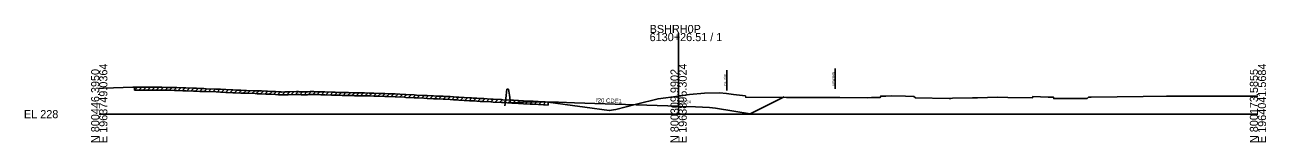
# Model space of a CAD drawing. Extents: x -26 to 1986619, y -10 to 827846.
# Drawn here: x -25.7 to 402.8, y 10490.3 to 10530.9 of the extents above; entities that cross this region are included whole.
import ezdxf

# ---------------------------------------------------------------- set-up
doc = ezdxf.new("R2010")
doc.units = 0
for name, color, linetype in [('Default', 7, 'Continuous'), ('RD_EX_Road', 7, 'Continuous'), ('RD_PD_ALT2_TrvlWay', 7, 'Continuous'), ('RD_PD_ALT5_LnLine', 7, 'Continuous'), ('RD_PD_ALT5_TrvlWay', 7, 'Continuous'), ('RD_PD_PaveDit', 7, 'Continuous'), ('RD_Sketch2', 7, 'Continuous'), ('RD_XS_ExRW', 7, 'Continuous'), ('RD_XS_NewRW', 7, 'Continuous')]:
    doc.layers.add(name, color=color, linetype=linetype)

msp = doc.modelspace()

# ---------------------------------------------------------------- linework, layer by layer
at = {"layer": 'RD_EX_Road'}
for p, q in [((200, 10500), (200, 10528.02)), ((0, 10500), (200, 10500)), ((200, 10500), (400, 10500))]:
    msp.add_line(p, q, dxfattribs=at)
at = {"layer": 'RD_PD_ALT5_LnLine'}
msp.add_lwpolyline([(0, 10508.87), (1.52, 10508.93), (4.94, 10509.05), (11.58, 10509.3), (12.32, 10509.3), (12.8, 10509.29), (13.3, 10509.34), (14.23, 10509.34), (15.37, 10509.34), (16.45, 10509.34), (17.13, 10509.34), (17.88, 10509.33), (18.87, 10509.31), (19.86, 10509.3), (21.57, 10509.28), (23.13, 10509.26), (24.28, 10509.25), (26, 10509.21), (26.8, 10509.18), (28.88, 10509.11), (29.87, 10509.08), (32.52, 10508.96), (33.06, 10508.94), (33.56, 10508.92), (34.75, 10508.86), (36.16, 10508.81), (36.93, 10508.78), (40.34, 10508.65), (41.83, 10508.59), (43.75, 10508.51), (46.1, 10508.39), (47.2, 10508.34), (48.91, 10508.28), (50.87, 10508.21), (53.82, 10508.1), (54.51, 10508.07), (56.05, 10508), (57.45, 10507.94), (58.07, 10507.92), (59.47, 10507.87), (60.85, 10507.79), (61.91, 10507.72), (62.16, 10507.68), (62.66, 10507.65), (63.08, 10507.63), (64.01, 10507.67), (65.2, 10507.68), (68.05, 10507.84), (68.68, 10507.79), (68.96, 10507.73), (69.66, 10507.72), (70.11, 10507.72), (70.8, 10507.71), (71.77, 10507.69), (72.07, 10507.76), (72.76, 10507.77), (74.13, 10507.77), (74.95, 10507.75), (76.52, 10507.7), (77.93, 10507.66), (80.17, 10507.59), (81.42, 10507.56), (82.55, 10507.52), (83.82, 10507.49), (84.92, 10507.46), (86.05, 10507.43), (87.52, 10507.4), (87.87, 10507.39), (88.22, 10507.38), (89.63, 10507.36), (91.54, 10507.31), (93.18, 10507.27), (94.82, 10507.23), (96.76, 10507.18), (98.64, 10507.11), (99.89, 10507.05), (102.2, 10506.96), (105.35, 10506.81), (105.85, 10506.79), (108.68, 10506.64), (109.51, 10506.59), (112.03, 10506.48), (113.17, 10506.43), (115.38, 10506.33), (116.81, 10506.26), (118.73, 10506.16), (119.56, 10506.12), (121.09, 10506.04), (122.33, 10505.96), (123.26, 10505.91), (124.13, 10505.86), (125.92, 10505.76), (127.84, 10505.64), (128.5, 10505.6), (129.13, 10505.56), (130.35, 10505.48), (131.51, 10505.41), (132.78, 10505.35), (135.16, 10505.21), (136, 10505.17), (138.81, 10505.02), (139.36, 10504.99), (142.48, 10504.81), (142.97, 10504.79), (146.42, 10504.6), (148.73, 10504.49), (149.8, 10504.43), (153.31, 10504.27), (153.99, 10504.26), (154.95, 10504.11), (163.34, 10503.02), (167.58, 10502.43), (176.05, 10501.21), (178.36, 10501.66), (185.49, 10503.49), (192.93, 10505.29), (200, 10506.24), (203.8, 10506.75), (208.97, 10507.29), (214.17, 10507.31), (216.56, 10507.17), (218.99, 10506.84), (223.09, 10506.27), (223.19, 10505.82), (237.25, 10505.78), (240.1, 10505.77), (247.06, 10505.8), (255.61, 10505.75), (265.3, 10505.66), (266.64, 10505.71), (268.44, 10505.75), (269.61, 10505.78), (269.77, 10506.23), (271.54, 10506.25), (273.49, 10506.27), (278.37, 10506.22), (281.21, 10506.13), (281.77, 10505.67), (293.38, 10505.45), (294.03, 10505.46), (294.58, 10505.48), (301.46, 10505.58), (302.65, 10505.61), (303.19, 10505.63), (310.11, 10505.81), (313.63, 10505.8), (322.19, 10505.69), (322.3, 10506.14), (327.53, 10505.87), (327.95, 10505.87), (328.29, 10505.86), (329.43, 10505.82), (329.53, 10505.38), (341, 10505.39), (341.5, 10505.84), (342.48, 10505.85), (360.36, 10506.11), (368.41, 10506.24), (393.13, 10506.23), (400, 10506.23)], dxfattribs=at)
at = {"layer": 'RD_PD_PaveDit'}
for p, q in [((12.2, 10508.3), (13.24, 10509.33)), ((12.2, 10508.3), (12.2, 10509.3)), ((12.2, 10508.3), (12.32, 10508.3)), ((12.32, 10508.3), (12.8, 10508.29)), ((12.8, 10508.29), (13.3, 10508.34)), ((13.3, 10508.34), (14.23, 10508.34)), ((13.7, 10508.34), (14.7, 10509.34)), ((14.23, 10508.34), (15.37, 10508.34)), ((15.2, 10508.34), (16.2, 10509.34)), ((15.37, 10508.34), (16.45, 10508.34)), ((16.45, 10508.34), (17.13, 10508.34)), ((16.7, 10508.34), (17.69, 10509.33)), ((17.13, 10508.34), (17.88, 10508.33)), ((17.88, 10508.33), (18.87, 10508.31)), ((18.2, 10508.32), (19.19, 10509.31)), ((18.87, 10508.31), (19.86, 10508.3)), ((19.7, 10508.3), (20.69, 10509.29)), ((19.86, 10508.3), (21.57, 10508.28)), ((21.2, 10508.28), (22.19, 10509.27)), ((21.57, 10508.28), (23.13, 10508.26)), ((22.7, 10508.26), (23.69, 10509.25)), ((23.13, 10508.26), (24.28, 10508.25)), ((24.2, 10508.25), (25.18, 10509.23)), ((24.28, 10508.25), (26, 10508.21)), ((25.7, 10508.21), (26.67, 10509.19)), ((26, 10508.21), (26.8, 10508.18)), ((26.8, 10508.18), (28.88, 10508.11)), ((27.2, 10508.17), (28.17, 10509.14)), ((28.7, 10508.12), (29.66, 10509.08)), ((28.88, 10508.11), (29.87, 10508.08)), ((29.87, 10508.08), (32.52, 10507.96)), ((30.2, 10508.06), (31.16, 10509.02)), ((31.7, 10508), (32.66, 10508.95)), ((32.52, 10507.96), (33.06, 10507.94)), ((33.06, 10507.94), (33.56, 10507.92)), ((33.2, 10507.93), (34.16, 10508.89)), ((33.56, 10507.92), (34.75, 10507.86)), ((34.7, 10507.87), (35.66, 10508.83)), ((34.75, 10507.86), (36.16, 10507.81)), ((36.16, 10507.81), (36.93, 10507.78)), ((36.2, 10507.81), (37.16, 10508.77)), ((36.93, 10507.78), (40.34, 10507.65)), ((37.7, 10507.75), (38.66, 10508.71)), ((39.2, 10507.69), (40.16, 10508.66)), ((40.34, 10507.65), (41.83, 10507.59)), ((40.7, 10507.64), (41.66, 10508.6)), ((42.2, 10507.58), (43.16, 10508.53)), ((43.7, 10507.51), (44.65, 10508.46)), ((45.2, 10507.44), (46.15, 10508.39)), ((46.7, 10507.36), (47.66, 10508.33)), ((48.2, 10507.31), (49.17, 10508.27)), ((49.7, 10507.26), (50.67, 10508.22)), ((51.2, 10507.2), (52.16, 10508.16)), ((52.7, 10507.14), (53.66, 10508.1)), ((54.2, 10507.08), (55.16, 10508.04)), ((55.7, 10507.02), (56.66, 10507.98)), ((57.2, 10506.95), (58.16, 10507.92)), ((58.7, 10506.9), (59.66, 10507.86)), ((60.2, 10506.83), (61.14, 10507.77)), ((61.7, 10506.73), (62.62, 10507.66)), ((63.2, 10506.64), (64.23, 10507.67)), ((64.7, 10506.67), (65.74, 10507.71)), ((66.2, 10506.73), (67.26, 10507.8)), ((67.7, 10506.82), (68.67, 10507.79)), ((69.2, 10506.72), (70.19, 10507.71)), ((70.7, 10506.71), (71.68, 10507.69)), ((72.2, 10506.76), (73.21, 10507.77)), ((73.7, 10506.77), (74.68, 10507.76)), ((75.2, 10506.74), (76.17, 10507.71)), ((76.7, 10506.69), (77.67, 10507.66)), ((78.2, 10506.65), (79.17, 10507.62)), ((41.83, 10507.59), (43.75, 10507.51)), ((43.75, 10507.51), (46.1, 10507.39)), ((46.1, 10507.39), (47.2, 10507.34)), ((47.2, 10507.34), (48.91, 10507.28)), ((48.91, 10507.28), (50.87, 10507.21)), ((50.87, 10507.21), (53.82, 10507.1)), ((53.82, 10507.1), (54.51, 10507.07)), ((54.51, 10507.07), (56.05, 10507)), ((56.05, 10507), (57.45, 10506.94)), ((57.45, 10506.94), (58.07, 10506.92)), ((58.07, 10506.92), (59.47, 10506.87)), ((59.47, 10506.87), (60.85, 10506.79)), ((60.85, 10506.79), (61.91, 10506.72)), ((61.91, 10506.72), (62.16, 10506.68)), ((62.16, 10506.68), (62.66, 10506.65)), ((62.66, 10506.65), (63.08, 10506.63)), ((63.08, 10506.63), (64.01, 10506.67)), ((64.01, 10506.67), (65.2, 10506.68)), ((65.2, 10506.68), (68.05, 10506.84)), ((68.05, 10506.84), (68.68, 10506.79)), ((68.68, 10506.79), (68.96, 10506.73)), ((68.96, 10506.73), (69.66, 10506.72)), ((69.66, 10506.72), (70.11, 10506.72)), ((70.11, 10506.72), (70.8, 10506.71)), ((70.8, 10506.71), (71.77, 10506.69)), ((71.77, 10506.69), (72.07, 10506.76)), ((72.07, 10506.76), (72.76, 10506.77)), ((72.76, 10506.77), (74.13, 10506.77)), ((74.13, 10506.77), (74.95, 10506.75)), ((74.95, 10506.75), (76.52, 10506.7)), ((76.52, 10506.7), (77.93, 10506.66)), ((77.93, 10506.66), (80.17, 10506.59)), ((79.7, 10506.61), (80.67, 10507.58)), ((80.17, 10506.59), (81.42, 10506.56)), ((81.2, 10506.56), (82.17, 10507.53)), ((81.42, 10506.56), (82.55, 10506.52)), ((82.55, 10506.52), (83.82, 10506.49)), ((82.7, 10506.52), (83.67, 10507.49)), ((83.82, 10506.49), (84.92, 10506.46)), ((84.2, 10506.48), (85.17, 10507.45)), ((84.92, 10506.46), (86.05, 10506.43)), ((85.7, 10506.43), (86.68, 10507.41)), ((86.05, 10506.43), (87.52, 10506.4)), ((87.2, 10506.4), (88.18, 10507.38)), ((87.52, 10506.4), (87.87, 10506.39)), ((87.87, 10506.39), (88.22, 10506.38)), ((88.22, 10506.38), (89.63, 10506.36)), ((88.7, 10506.37), (89.68, 10507.36)), ((89.63, 10506.36), (91.54, 10506.31)), ((90.2, 10506.34), (91.18, 10507.32)), ((91.54, 10506.31), (93.18, 10506.27)), ((91.7, 10506.31), (92.68, 10507.29)), ((93.18, 10506.27), (94.82, 10506.23)), ((93.2, 10506.27), (94.18, 10507.25)), ((94.7, 10506.24), (95.67, 10507.21)), ((94.82, 10506.23), (96.76, 10506.18)), ((96.2, 10506.2), (97.17, 10507.16)), ((96.76, 10506.18), (98.64, 10506.11)), ((97.7, 10506.14), (98.66, 10507.1)), ((98.64, 10506.11), (99.89, 10506.05)), ((99.2, 10506.08), (100.16, 10507.04)), ((99.89, 10506.05), (102.2, 10505.96)), ((100.7, 10506.02), (101.66, 10506.98)), ((102.2, 10505.96), (103.16, 10506.91)), ((102.2, 10505.96), (105.35, 10505.81)), ((103.7, 10505.89), (104.66, 10506.84)), ((105.2, 10505.82), (106.15, 10506.77)), ((105.35, 10505.81), (105.85, 10505.79)), ((105.85, 10505.79), (108.68, 10505.64)), ((106.7, 10505.74), (107.65, 10506.69)), ((108.2, 10505.66), (109.15, 10506.61)), ((108.68, 10505.64), (109.51, 10505.59)), ((109.51, 10505.59), (112.03, 10505.48)), ((109.7, 10505.59), (110.66, 10506.54)), ((111.2, 10505.52), (112.16, 10506.47)), ((112.03, 10505.48), (113.17, 10505.43)), ((112.7, 10505.45), (113.66, 10506.41)), ((113.17, 10505.43), (115.38, 10505.33)), ((114.2, 10505.38), (115.16, 10506.34)), ((115.38, 10505.33), (116.81, 10505.26)), ((115.7, 10505.31), (116.65, 10506.26)), ((116.81, 10505.26), (118.73, 10505.16)), ((117.2, 10505.24), (118.15, 10506.19)), ((118.7, 10505.16), (119.65, 10506.12)), ((118.73, 10505.16), (119.56, 10505.12)), ((119.56, 10505.12), (121.09, 10505.04)), ((120.2, 10505.09), (121.15, 10506.03)), ((121.09, 10505.04), (122.33, 10504.96)), ((121.7, 10505), (122.64, 10505.95)), ((122.33, 10504.96), (123.26, 10504.91)), ((123.2, 10504.91), (124.15, 10505.86)), ((123.26, 10504.91), (124.13, 10504.86)), ((124.13, 10504.86), (125.92, 10504.76)), ((124.7, 10504.83), (125.65, 10505.77)), ((125.92, 10504.76), (127.84, 10504.64)), ((126.2, 10504.74), (127.14, 10505.68)), ((127.7, 10504.65), (128.64, 10505.59)), ((127.84, 10504.64), (128.5, 10504.6)), ((128.5, 10504.6), (129.13, 10504.56)), ((129.13, 10504.56), (130.35, 10504.48)), ((129.2, 10504.55), (130.14, 10505.49)), ((130.35, 10504.48), (131.51, 10504.41)), ((130.7, 10504.46), (131.65, 10505.41)), ((131.51, 10504.41), (132.78, 10504.35)), ((132.2, 10504.38), (133.15, 10505.33)), ((132.78, 10504.35), (135.16, 10504.21)), ((133.7, 10504.3), (134.65, 10505.24)), ((135.16, 10504.21), (136, 10504.17)), ((135.2, 10504.21), (136.15, 10505.16)), ((136, 10504.17), (138.81, 10504.02)), ((136.7, 10504.13), (137.65, 10505.08)), ((138.2, 10504.05), (139.15, 10505)), ((138.81, 10504.02), (139.36, 10503.99)), ((139.36, 10503.99), (142.48, 10503.81)), ((139.7, 10503.97), (140.65, 10504.92)), ((141.2, 10503.89), (142.15, 10504.83)), ((142.48, 10503.81), (142.97, 10503.79)), ((142.7, 10503.8), (143.65, 10504.75)), ((142.97, 10503.79), (146.42, 10503.6)), ((144.2, 10503.72), (145.15, 10504.67)), ((145.7, 10503.64), (146.65, 10504.59)), ((146.42, 10503.6), (148.73, 10503.49)), ((147.2, 10503.56), (148.15, 10504.52)), ((148.7, 10503.49), (149.65, 10504.44)), ((148.73, 10503.49), (149.8, 10503.43)), ((149.8, 10503.43), (153.31, 10503.27)), ((150.2, 10503.41), (151.15, 10504.37)), ((151.7, 10503.34), (152.65, 10504.3)), ((153.2, 10503.27), (154.16, 10504.23)), ((154.95, 10504.11), (154.95, 10503.11)), ((153.31, 10503.27), (153.99, 10503.26)), ((153.99, 10503.26), (154.95, 10503.11))]:
    msp.add_line(p, q, dxfattribs=at)
at = {"layer": 'RD_Sketch2'}
msp.add_lwpolyline([(140, 10502.91), (140.33, 10505.42), (140.75, 10508.58), (141.25, 10508.58), (141.58, 10506.51), (142, 10503.91), (146.5, 10504.08), (152.02, 10504.3), (158.49, 10504.09), (164.03, 10503.9), (181.65, 10503.32), (200, 10502.72), (200.71, 10502.69), (205.84, 10502.48), (210.71, 10502.28), (211.74, 10502.2), (212.71, 10502.12), (219.04, 10501.06), (224.71, 10500.11), (230.74, 10503.12), (236.44, 10505.96)], dxfattribs=at)
at = {"layer": 'RD_XS_ExRW'}
msp.add_line((216.65, 10508.16), (216.65, 10515.16), dxfattribs=at)
at = {"layer": 'RD_XS_NewRW'}
msp.add_line((254.08, 10508.74), (254.08, 10515.74), dxfattribs=at)

# ---------------------------------------------------------------- texts
at = {"layer": 'Default'}
msp.add_text('-', height=0.0001, dxfattribs=at).set_placement((0, 10500))
at = {"layer": 'RD_EX_Road'}
for s, p in [('BSHRH0P', (190, 10528.02)), ('6130+26.51 / 1', (190, 10525.22)), ('EL 228', (-26, 10498.6))]:
    msp.add_text(s, height=2.8, dxfattribs=at).set_placement(p)
for s, p in [('E 1963749.0364', (2.8, 10490)), ('E 1963895.3024', (202.8, 10490)), ('E 1964041.5684', (402.8, 10490)), ('N 800446.3950', (0, 10490)), ('N 800309.9902', (200, 10490)), ('N 800173.5855', (400, 10490))]:
    msp.add_text(s, height=2.8, rotation=90, dxfattribs=at).set_placement(p)
at = {"layer": 'RD_PD_ALT2_TrvlWay'}
msp.add_text('I20 CDE1', height=1.5, rotation=358.0852, dxfattribs=at).set_placement((171.48, 10504.05))
at = {"layer": 'RD_PD_ALT5_TrvlWay'}
msp.add_text('234.24', height=1, dxfattribs=at).set_placement((200, 10503.74))
at = {"layer": 'RD_XS_ExRW'}
msp.add_text('EX. R/W ', height=0.75, rotation=90, dxfattribs=at).set_placement((216.4, 10509.83))
at = {"layer": 'RD_XS_NewRW'}
msp.add_text('NEW R/W ', height=0.75, rotation=90, dxfattribs=at).set_placement((253.83, 10509.87))

doc.saveas('drawing.dxf')
